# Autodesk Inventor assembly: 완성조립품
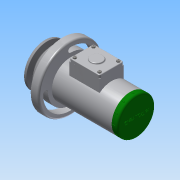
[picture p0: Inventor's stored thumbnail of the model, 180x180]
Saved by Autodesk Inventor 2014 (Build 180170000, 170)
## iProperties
Created: 2017-05
Part Number: 완성조립품
Document SubType Name: Assembly
Designer: Administrator
Author: Administrator
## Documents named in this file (18)
- C:\Users\Administrator\Desktop\470507V1004\완성조립품.iam
- C:\Users\Administrator\Desktop\470507V1004\본체.ipt
- C:\Users\Administrator\Desktop\470507V1004\축.ipt
- C:\Users\Administrator\Desktop\470507V1004\부시1.ipt
- C:\Users\Administrator\Desktop\470507V1004\베어링 15 x 35 x 11.ipt
- C:\Users\Administrator\Desktop\470507V1004\멈춤링 35x1.6.ipt
- C:\Users\Administrator\Desktop\470507V1004\부시2.ipt
- C:\Users\Administrator\Desktop\470507V1004\와셔 10x21.ipt
- C:\Users\Administrator\Desktop\470507V1004\너트 M10.ipt
- C:\Users\Administrator\Desktop\470507V1004\사이드 커버.ipt
- 사이드 커버.ipt
- C:\Users\Administrator\Desktop\470507V1004\멈춤링 15 x 1.ipt
- C:\Users\Administrator\Desktop\470507V1004\오일 실 15 25 7.ipt
- C:\Users\Administrator\Desktop\470507V1004\키 4 x 4 x 18.ipt
- C:\Users\Administrator\Desktop\470507V1004\V-벨트풀리.ipt
- C:\Users\Administrator\Desktop\470507V1004\볼트 M4 x 10.ipt
- C:\Users\Administrator\Desktop\470507V1004\탑 커버.ipt
- C:\Users\Administrator\Desktop\470507V1004\십자볼트 M3 x 10.ipt
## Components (2 placed, 2 different names)
1. V-벨트풀리:1
2. ISO 4017 M4 x 10:1 — 각도:6
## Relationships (1: Angle 1)
- 각도:6 [Angle]: ISO 4017 M4 x 10:1
